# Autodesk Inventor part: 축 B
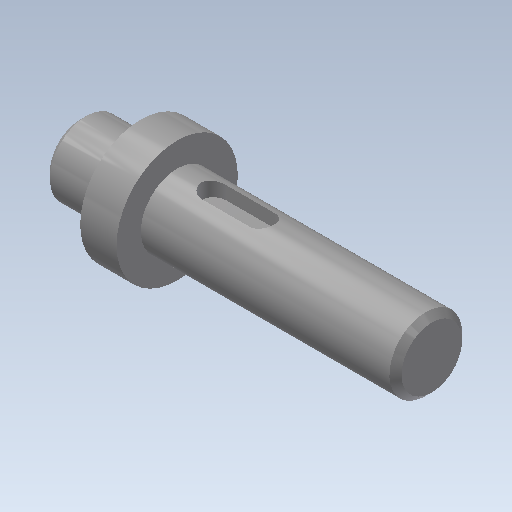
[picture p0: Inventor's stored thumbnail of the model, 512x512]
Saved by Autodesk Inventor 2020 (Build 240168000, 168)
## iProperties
Created: 2020-04
Part Number: 축 B
Material: 강철, 연강
Document SubType Name: Modeling
Designer: mduedu
Density: 7.86 g/cm^3
Mass: 57.2004 g
Surface Area: 29.0657 cm^2
Volume: 7.2774 cm^3
Appearance: 강철
Author: mduedu
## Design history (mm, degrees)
revolve "회전1" stored, may be unused: angle "d11" = 90 deg
sketch "스케치3"
  geometry: L1 (0, -6)-(0, 6) reference; L2 (0, 6)-(10, 6) reference; L3 (10, 6)-(10, 10) reference; L4 (10, 10)-(16, 10) reference; L5 (16, 10)-(16, 6) reference; L6 (16, 6)-(58, 6) reference; L7 (58, 6)-(58, -6) reference; L8 (58, -6)-(16, -6) reference; L9 (16, -6)-(16, -10) reference; L10 (16, -10)-(10, -10) reference; L11 (10, -10)-(10, -6) reference; L12 (10, -6)-(0, -6) reference; L13 (20, 6)-(32, 6); L14 (32, 6)-(32, 3.5); L15 (32, 3.5)-(20, 3.5); L16 (20, 3.5)-(20, 6); 1 further point
  constraints: 8 end point, 2 parallel, 1 horizontal, 1 perpendicular, 1 point on line
  dimensions: "d17" = 12 distance of L14.end L15.end; "d18" = 2.5 distance of L13.end L14.end; "d19" = 4 distance from line of L16 L4.end
extrude "돌출2" cut sketch "스케치3" stored distance "d20" = 4; taper "d21" = 0 deg
fillet "모깎기2" dims "d22" = 2
chamfer "모따기1" distance "d23" = 1; stored, may be unused: second distance "d24" = 2, angle "d25" = 45 deg
chamfer "모따기2" distance "d26" = 1; stored, may be unused: second distance "d27" = 2, angle "d28" = 45 deg
fillet "모깎기3" dims "d29" = 0.3
node "솔리드1"
sketch "스케치1"
  geometry: L1 (0, 0)-(10, 0); L2 (10, 0)-(10, 6); L3 (10, 6)-(0, 6); L4 (0, 6)-(0, 0); L5 (10, 0)-(16, 0); L6 (16, 0)-(16, 10); L7 (16, 10)-(10, 10); L8 (10, 10)-(10, 0); L9 (16, 0)-(58, 0); L10 (58, 0)-(58, 6); L11 (58, 6)-(16, 6); L12 (16, 6)-(16, 0); L13 (58, 0)-(58, 0); L14 (58, 5)-(58, 0)
  constraints: 28 end point, 6 parallel, 4 horizontal, 3 perpendicular
  dimensions: "d2" = 10 distance of L2.end L3.end; "d3" = 6 distance of L6.end L7.end; "d7" = 12 diameter of L11 L9; "d8" = 12 diameter of L3 L1; "d9" = 20 diameter of L7 L5; "d36" = 58 distance between parallel lines of L10 L4
node "절단 모서리 투영2"
